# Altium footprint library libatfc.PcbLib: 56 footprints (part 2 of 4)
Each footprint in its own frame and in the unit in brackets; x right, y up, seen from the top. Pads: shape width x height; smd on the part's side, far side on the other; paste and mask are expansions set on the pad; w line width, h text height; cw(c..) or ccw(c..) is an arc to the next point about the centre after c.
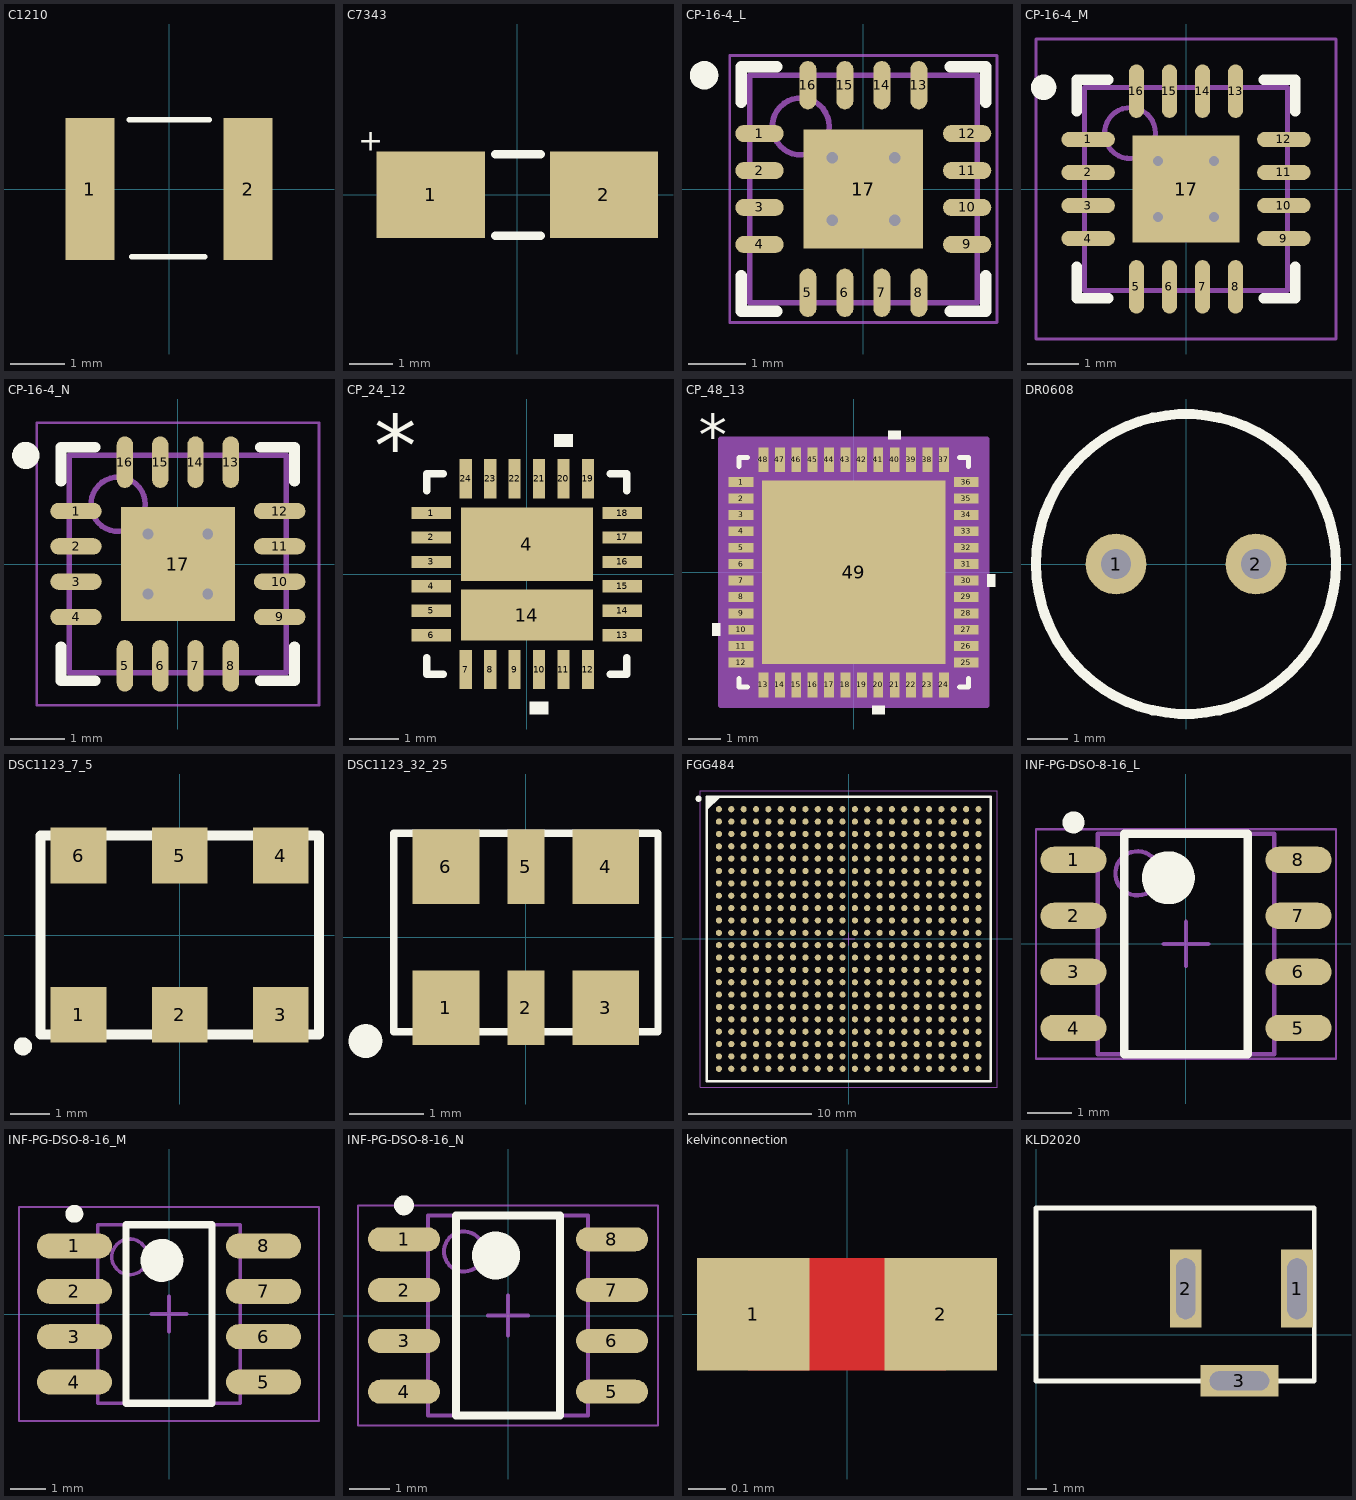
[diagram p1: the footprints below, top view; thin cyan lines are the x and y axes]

## C1210 [mm]
pads (2):
  rect 0.9x2.6 smd: 1(-1.45,0) 2(1.45,0)
Top Overlay:
  lines w0.1: -0.728,1.27 0.737,1.27 ; -0.687,-1.245 0.66,-1.245
3D body: height 0.55, standoff 0, extent -1.524,-1.143 -1.016,1.143
3D body: height 0.55, standoff 0, extent -1.016,-1.143 1.016,1.143
3D body: height 0.55, standoff 0, extent 1.016,-1.143 1.524,1.143

## C7343 [mm]
pads (2):
  rect 2.5x2 smd: 1(-2,0) 2(2,0)
Top Overlay:
  lines w0.2: -0.508,-0.94 0.533,-0.94 ; -0.508,0.94 0.533,0.94
  text "+" at -3.683,1.016 h0.51

## CP-16-4_L [mm] "QFN, 16-Leads, Body 4x4mm, Pitch 0.65mm, Thermal Pad 2.1x2.1mm, IPC High Density"
height 1
pads (17):
  oval 0.85x0.3 smd: 1(-1.825,0.975) 2(-1.825,0.325) 3(-1.825,-0.325) 4(-1.825,-0.975) 9(1.825,-0.975) 10(1.825,-0.325) 11(1.825,0.325) 12(1.825,0.975)
  oval 0.3x0.85 smd: 5(-0.975,-1.825) 6(-0.325,-1.825) 7(0.325,-1.825) 8(0.975,-1.825) 13(0.975,1.825) 14(0.325,1.825) 15(-0.325,1.825) 16(-0.975,1.825)
  rect 2.1x2.1 smd: 17(0,0)
via 0.55,-0.55 diameter 0.5 hole 0.2
via -0.55,-0.55 diameter 0.5 hole 0.2
via 0.55,0.55 diameter 0.5 hole 0.2
via -0.55,0.55 diameter 0.5 hole 0.2
Top Overlay:
  circle w0.25: c-2.8,2 r0.125
  lines w0.2: -2.15,-1.525 -2.15,-2.15 -1.525,-2.15 ; -2.15,1.525 -2.15,2.15 -1.525,2.15 ; 1.525,-2.15 2.15,-2.15 2.15,-1.525 ; 1.525,2.15 2.15,2.15 2.15,1.525
Mechanical 13:
  circle w0.1: c-1.1,1.1 r0.5
  lines w0.1: -2,-2 2,-2 2,2 -2,2 -2,-2
Mechanical 15:
  lines w0.05: -2.35,-2.35 2.35,-2.35 2.35,2.35 -2.35,2.35 -2.35,-2.35
  lines w0.1: -0.5,0 0.5,0 ; 0,-0.5 0,0.5
3D body: height 1, standoff 0, extent -2,-2 2,2

## CP-16-4_M [mm] "QFN, 16-Leads, Body 4x4mm, Pitch 0.65mm, Thermal Pad 2.1x2.1mm, IPC Low Density"
height 1
pads (17):
  oval 1.05x0.3 smd: 1(-1.925,0.975) 2(-1.925,0.325) 3(-1.925,-0.325) 4(-1.925,-0.975) 9(1.925,-0.975) 10(1.925,-0.325) 11(1.925,0.325) 12(1.925,0.975)
  oval 0.3x1.05 smd: 5(-0.975,-1.925) 6(-0.325,-1.925) 7(0.325,-1.925) 8(0.975,-1.925) 13(0.975,1.925) 14(0.325,1.925) 15(-0.325,1.925) 16(-0.975,1.925)
  rect 2.1x2.1 smd: 17(0,0)
via 0.55,-0.55 diameter 0.5 hole 0.2
via -0.55,-0.55 diameter 0.5 hole 0.2
via 0.55,0.55 diameter 0.5 hole 0.2
via -0.55,0.55 diameter 0.5 hole 0.2
Top Overlay:
  circle w0.25: c-2.8,2 r0.125
  lines w0.2: -2.15,-1.525 -2.15,-2.15 -1.525,-2.15 ; -2.15,1.525 -2.15,2.15 -1.525,2.15 ; 1.525,-2.15 2.15,-2.15 2.15,-1.525 ; 1.525,2.15 2.15,2.15 2.15,1.525
Mechanical 13:
  circle w0.1: c-1.1,1.1 r0.5
  lines w0.1: -2,-2 2,-2 2,2 -2,2 -2,-2
Mechanical 15:
  lines w0.05: -2.95,-2.95 2.95,-2.95 2.95,2.95 -2.95,2.95 -2.95,-2.95
  lines w0.1: -0.5,0 0.5,0 ; 0,-0.5 0,0.5
3D body: height 1, standoff 0, extent -2,-2 2,2

## CP-16-4_N [mm] "QFN, 16-Leads, Body 4x4mm, Pitch 0.65mm, Thermal Pad 2.1x2.1mm, IPC Medium Density"
height 1
pads (17):
  oval 0.95x0.3 smd: 1(-1.875,0.975) 2(-1.875,0.325) 3(-1.875,-0.325) 4(-1.875,-0.975) 9(1.875,-0.975) 10(1.875,-0.325) 11(1.875,0.325) 12(1.875,0.975)
  oval 0.3x0.95 smd: 5(-0.975,-1.875) 6(-0.325,-1.875) 7(0.325,-1.875) 8(0.975,-1.875) 13(0.975,1.875) 14(0.325,1.875) 15(-0.325,1.875) 16(-0.975,1.875)
  rect 2.1x2.1 smd: 17(0,0)
via -0.55,0.55 diameter 0.5 hole 0.2
via 0.55,0.55 diameter 0.5 hole 0.2
via -0.55,-0.55 diameter 0.5 hole 0.2
via 0.55,-0.55 diameter 0.5 hole 0.2
Top Overlay:
  circle w0.25: c-2.8,2 r0.125
  lines w0.2: -2.15,-1.525 -2.15,-2.15 -1.525,-2.15 ; -2.15,1.525 -2.15,2.15 -1.525,2.15 ; 1.525,-2.15 2.15,-2.15 2.15,-1.525 ; 1.525,2.15 2.15,2.15 2.15,1.525
Mechanical 13:
  circle w0.1: c-1.1,1.1 r0.5
  lines w0.1: -2,-2 -2,2 2,2 2,-2 -2,-2
Mechanical 15:
  lines w0.05: -2.6,-2.6 -2.6,2.6 2.6,2.6 2.6,-2.6 -2.6,-2.6
  lines w0.1: -0.5,0 0.5,0 ; 0,-0.5 0,0.5
3D body: height 1, standoff 0, extent -2,-2 2,2

## CP_24_12 [mm]
pads (26):
  rect 0.805x0.25 smd: 1(-1.952,1.25) 2(-1.952,0.75) 3(-1.952,0.25) 4(-1.952,-0.25) 5(-1.952,-0.75) 6(-1.952,-1.25) 13(1.952,-1.25) 14(1.952,-0.75) 15(1.952,-0.25) 16(1.952,0.25) 17(1.952,0.75) 18(1.952,1.25)
  rect 2.7x1.5 smd: 4(0,0.61)
  rect 0.25x0.805 smd: 7(-1.25,-1.952) 8(-0.75,-1.952) 9(-0.25,-1.952) 10(0.25,-1.952) 11(0.75,-1.952) 12(1.25,-1.952) 19(1.25,1.952) 20(0.75,1.952) 21(0.25,1.952) 22(-0.25,1.952) 23(-0.75,1.952) 24(-1.25,1.952)
  rect 2.7x1.05 smd: 14(0,-0.838)
Top Overlay:
  region: 0.941,2.609 0.56,2.609 0.56,2.863 0.941,2.863
  region: 0.44,-2.609 0.059,-2.609 0.059,-2.863 0.44,-2.863
  lines w0.152: -2.05,-1.708 -2.05,-2.05 -1.708,-2.05 ; -2.05,1.708 -2.05,2.05 -1.708,2.05 ; 1.708,-2.05 2.05,-2.05 2.05,-1.708 ; 1.708,2.05 2.05,2.05 2.05,1.708
  text "*" at -3.124,2.007 h1.27
Mechanical 13:
  text "*" at -3.124,2.007 h1.27
3D body: height 0.25, standoff 0, extent -2.032,-2.032 2.032,2.032

## CP_48_13 [mm]
pads (49):
  rect 0.755x0.3 smd: 1(-3.433,2.75) 2(-3.433,2.25) 3(-3.433,1.75) 4(-3.433,1.25) 5(-3.433,0.75) 6(-3.433,0.25) 7(-3.433,-0.25) 8(-3.433,-0.75) 9(-3.433,-1.25) 10(-3.433,-1.75) 11(-3.433,-2.25) 12(-3.433,-2.75) 25(3.433,-2.75) 26(3.433,-2.25) 27(3.433,-1.75) 28(3.433,-1.25) 29(3.433,-0.75) 30(3.433,-0.25) 31(3.433,0.25) 32(3.433,0.75) 33(3.433,1.25) 34(3.433,1.75) 35(3.433,2.25) 36(3.433,2.75)
  rect 0.3x0.755 smd: 13(-2.75,-3.433) 14(-2.25,-3.433) 15(-1.75,-3.433) 16(-1.25,-3.433) 17(-0.75,-3.433) 18(-0.25,-3.433) 19(0.25,-3.433) 20(0.75,-3.433) 21(1.25,-3.433) 22(1.75,-3.433) 23(2.25,-3.433) 24(2.75,-3.433) 37(2.75,3.433) 38(2.25,3.433) 39(1.75,3.433) 40(1.25,3.433) 41(0.75,3.433) 42(0.25,3.433) 43(-0.25,3.433) 44(-0.75,3.433) 45(-1.25,3.433) 46(-1.75,3.433) 47(-2.25,3.433) 48(-2.75,3.433)
  rect 5.6x5.6 smd mask-2.781: 49(0,0)
Top Overlay:
  region: 1.441,4.064 1.06,4.064 1.06,4.318 1.441,4.318
  region: 4.064,-0.059 4.318,-0.059 4.318,-0.44 4.064,-0.44
  region: 0.941,-4.064 0.56,-4.064 0.56,-4.318 0.941,-4.318
  region: -4.064,-1.559 -4.318,-1.559 -4.318,-1.94 -4.064,-1.94
  lines w0.152: -3.5,-3.233 -3.5,-3.5 -3.233,-3.5 ; -3.5,3.233 -3.5,3.5 -3.233,3.5 ; 3.233,-3.5 3.5,-3.5 3.5,-3.233 ; 3.233,3.5 3.5,3.5 3.5,3.233
  text "*" at -4.724,3.556 h1.27
Mechanical 13:
  text "*" at -4.724,3.556 h1.27
Mechanical 15:
  region: 4.064,-4.064 -4.064,-4.064 -4.064,4.064 4.064,4.064
  lines w0.152: -4.064,-4.064 4.064,-4.064 4.064,4.064 -4.064,4.064 -4.064,-4.064
3D body: height 0.25, standoff 0, extent 0,0 0.254,0.254
3D body: height 0.76, standoff 0, extent -3.429,-3.429 3.404,3.404

## DR0608 [mil]
pads (2):
  round 60 hole 30: 1(-68.9,0) 2(68.9,0)
Top Overlay:
  circle w10: c0,0 r147.64
3D body "Coilcraft-DR0608.step": height 381.89, standoff -188.98, extent -148.63,-145.63 146.64,149.64

## DSC1123_7_5 [mm]
height 0.85
pads (6):
  rect 1.4x1.4 smd: 1(-2.54,-2) 2(0,-2) 3(2.54,-2) 4(2.54,2) 5(0,2) 6(-2.54,2)
Top Overlay:
  circle w0.254: c-3.937,-2.794 r0.1
  lines w0.254: -3.5,-2.5 3.5,-2.5 3.5,2.5 -3.5,2.5 -3.5,-2.5
3D body: height 0.85, standoff 0, extent -3.429,-2.413 3.429,2.413

## DSC1123_32_25 [mm]
pads (6):
  rect 0.9x1 smd: 1(-1.075,-0.95) 3(1.075,-0.95) 4(1.075,0.95) 6(-1.075,0.95)
  rect 0.5x1 smd: 2(0,-0.95) 5(0,0.95)
Top Overlay:
  circle w0.254: c-2.159,-1.397 r0.1
  lines w0.1: -1.778,-1.27 1.778,-1.27 1.778,1.397 -1.778,1.397 -1.778,-1.27
3D body: height 0.85, standoff 0, extent -1.778,-1.27 1.778,1.397

## FGG484 [mm] "BGA, 484-Balls, Body 23x23mm, Pitch 1mm"
height 2.6
pads (484):
  round 0.5 smd: A1(-10.5,10.5) A2(-9.5,10.5) A3(-8.5,10.5) A4(-7.5,10.5) A5(-6.5,10.5) A6(-5.5,10.5) A7(-4.5,10.5) A8(-3.5,10.5) A9(-2.5,10.5) A10(-1.5,10.5) A11(-0.5,10.5) A12(0.5,10.5) A13(1.5,10.5) A14(2.5,10.5) A15(3.5,10.5) A16(4.5,10.5) A17(5.5,10.5) A18(6.5,10.5) A19(7.5,10.5) A20(8.5,10.5) A21(9.5,10.5) A22(10.5,10.5) AA1(-10.5,-9.5) AA2(-9.5,-9.5) AA3(-8.5,-9.5) AA4(-7.5,-9.5) AA5(-6.5,-9.5) AA6(-5.5,-9.5) AA7(-4.5,-9.5) AA8(-3.5,-9.5) AA9(-2.5,-9.5) AA10(-1.5,-9.5) AA11(-0.5,-9.5) AA12(0.5,-9.5) AA13(1.5,-9.5) AA14(2.5,-9.5) AA15(3.5,-9.5) AA16(4.5,-9.5) AA17(5.5,-9.5) AA18(6.5,-9.5) AA19(7.5,-9.5) AA20(8.5,-9.5) AA21(9.5,-9.5) AA22(10.5,-9.5) AB1(-10.5,-10.5) AB2(-9.5,-10.5) AB3(-8.5,-10.5) AB4(-7.5,-10.5) AB5(-6.5,-10.5) AB6(-5.5,-10.5) AB7(-4.5,-10.5) AB8(-3.5,-10.5) AB9(-2.5,-10.5) AB10(-1.5,-10.5) AB11(-0.5,-10.5) AB12(0.5,-10.5) AB13(1.5,-10.5) AB14(2.5,-10.5) AB15(3.5,-10.5) AB16(4.5,-10.5) AB17(5.5,-10.5) AB18(6.5,-10.5) AB19(7.5,-10.5) AB20(8.5,-10.5) AB21(9.5,-10.5) AB22(10.5,-10.5) B1(-10.5,9.5) B2(-9.5,9.5) B3(-8.5,9.5) B4(-7.5,9.5) B5(-6.5,9.5) B6(-5.5,9.5) B7(-4.5,9.5) B8(-3.5,9.5) B9(-2.5,9.5) B10(-1.5,9.5) B11(-0.5,9.5) B12(0.5,9.5) B13(1.5,9.5) B14(2.5,9.5) B15(3.5,9.5) B16(4.5,9.5) B17(5.5,9.5) B18(6.5,9.5) B19(7.5,9.5) B20(8.5,9.5) B21(9.5,9.5) B22(10.5,9.5) C1(-10.5,8.5) C2(-9.5,8.5) C3(-8.5,8.5) C4(-7.5,8.5) C5(-6.5,8.5) C6(-5.5,8.5) C7(-4.5,8.5) C8(-3.5,8.5) C9(-2.5,8.5) C10(-1.5,8.5) C11(-0.5,8.5) C12(0.5,8.5) C13(1.5,8.5) C14(2.5,8.5) C15(3.5,8.5) C16(4.5,8.5) C17(5.5,8.5) C18(6.5,8.5) C19(7.5,8.5) C20(8.5,8.5) C21(9.5,8.5) C22(10.5,8.5) D1(-10.5,7.5) D2(-9.5,7.5) D3(-8.5,7.5) D4(-7.5,7.5) D5(-6.5,7.5) D6(-5.5,7.5) D7(-4.5,7.5) D8(-3.5,7.5) D9(-2.5,7.5) D10(-1.5,7.5) D11(-0.5,7.5) D12(0.5,7.5) D13(1.5,7.5) D14(2.5,7.5) D15(3.5,7.5) D16(4.5,7.5) D17(5.5,7.5) D18(6.5,7.5) D19(7.5,7.5) D20(8.5,7.5) D21(9.5,7.5) D22(10.5,7.5) E1(-10.5,6.5) E2(-9.5,6.5) E3(-8.5,6.5) E4(-7.5,6.5) E5(-6.5,6.5) E6(-5.5,6.5) E7(-4.5,6.5) E8(-3.5,6.5) E9(-2.5,6.5) E10(-1.5,6.5) E11(-0.5,6.5) E12(0.5,6.5) E13(1.5,6.5) E14(2.5,6.5) E15(3.5,6.5) E16(4.5,6.5) E17(5.5,6.5) E18(6.5,6.5) E19(7.5,6.5) E20(8.5,6.5) E21(9.5,6.5) E22(10.5,6.5) F1(-10.5,5.5) F2(-9.5,5.5) F3(-8.5,5.5) F4(-7.5,5.5) F5(-6.5,5.5) F6(-5.5,5.5) F7(-4.5,5.5) F8(-3.5,5.5) F9(-2.5,5.5) F10(-1.5,5.5) F11(-0.5,5.5) F12(0.5,5.5) F13(1.5,5.5) F14(2.5,5.5) F15(3.5,5.5) F16(4.5,5.5) F17(5.5,5.5) F18(6.5,5.5) F19(7.5,5.5) F20(8.5,5.5) F21(9.5,5.5) F22(10.5,5.5) G1(-10.5,4.5) G2(-9.5,4.5) G3(-8.5,4.5) G4(-7.5,4.5) G5(-6.5,4.5) G6(-5.5,4.5) G7(-4.5,4.5) G8(-3.5,4.5) G9(-2.5,4.5) G10(-1.5,4.5) G11(-0.5,4.5) G12(0.5,4.5) G13(1.5,4.5) G14(2.5,4.5) G15(3.5,4.5) G16(4.5,4.5) G17(5.5,4.5) G18(6.5,4.5) G19(7.5,4.5) G20(8.5,4.5) G21(9.5,4.5) G22(10.5,4.5) H1(-10.5,3.5) H2(-9.5,3.5) H3(-8.5,3.5) H4(-7.5,3.5) H5(-6.5,3.5) H6(-5.5,3.5) H7(-4.5,3.5) H8(-3.5,3.5) H9(-2.5,3.5) H10(-1.5,3.5) H11(-0.5,3.5) H12(0.5,3.5) H13(1.5,3.5) H14(2.5,3.5) H15(3.5,3.5) H16(4.5,3.5) H17(5.5,3.5) H18(6.5,3.5) H19(7.5,3.5) H20(8.5,3.5) H21(9.5,3.5) H22(10.5,3.5) J1(-10.5,2.5) J2(-9.5,2.5) J3(-8.5,2.5) J4(-7.5,2.5) J5(-6.5,2.5) J6(-5.5,2.5) J7(-4.5,2.5) J8(-3.5,2.5) J9(-2.5,2.5) J10(-1.5,2.5) J11(-0.5,2.5) J12(0.5,2.5) J13(1.5,2.5) J14(2.5,2.5) J15(3.5,2.5) J16(4.5,2.5) J17(5.5,2.5) J18(6.5,2.5) J19(7.5,2.5) J20(8.5,2.5) J21(9.5,2.5) J22(10.5,2.5) K1(-10.5,1.5) K2(-9.5,1.5) K3(-8.5,1.5) K4(-7.5,1.5) K5(-6.5,1.5) K6(-5.5,1.5) K7(-4.5,1.5) K8(-3.5,1.5) K9(-2.5,1.5) K10(-1.5,1.5) K11(-0.5,1.5) K12(0.5,1.5) K13(1.5,1.5) K14(2.5,1.5) K15(3.5,1.5) K16(4.5,1.5) K17(5.5,1.5) K18(6.5,1.5) K19(7.5,1.5) K20(8.5,1.5) K21(9.5,1.5) K22(10.5,1.5) L1(-10.5,0.5) L2(-9.5,0.5) L3(-8.5,0.5) L4(-7.5,0.5) L5(-6.5,0.5) L6(-5.5,0.5) L7(-4.5,0.5) L8(-3.5,0.5) L9(-2.5,0.5) L10(-1.5,0.5) L11(-0.5,0.5) L12(0.5,0.5) L13(1.5,0.5) L14(2.5,0.5) L15(3.5,0.5) L16(4.5,0.5) L17(5.5,0.5) L18(6.5,0.5) L19(7.5,0.5) L20(8.5,0.5) L21(9.5,0.5) L22(10.5,0.5) M1(-10.5,-0.5) M2(-9.5,-0.5) M3(-8.5,-0.5) M4(-7.5,-0.5) M5(-6.5,-0.5) M6(-5.5,-0.5) M7(-4.5,-0.5) M8(-3.5,-0.5) M9(-2.5,-0.5) M10(-1.5,-0.5) M11(-0.5,-0.5) M12(0.5,-0.5) M13(1.5,-0.5) M14(2.5,-0.5) M15(3.5,-0.5) M16(4.5,-0.5) M17(5.5,-0.5) M18(6.5,-0.5) M19(7.5,-0.5) M20(8.5,-0.5) M21(9.5,-0.5) M22(10.5,-0.5) N1(-10.5,-1.5) N2(-9.5,-1.5) N3(-8.5,-1.5) N4(-7.5,-1.5) N5(-6.5,-1.5) N6(-5.5,-1.5) N7(-4.5,-1.5) N8(-3.5,-1.5) N9(-2.5,-1.5) N10(-1.5,-1.5) N11(-0.5,-1.5) N12(0.5,-1.5) N13(1.5,-1.5) N14(2.5,-1.5) N15(3.5,-1.5) N16(4.5,-1.5) N17(5.5,-1.5) N18(6.5,-1.5) N19(7.5,-1.5) N20(8.5,-1.5) N21(9.5,-1.5) N22(10.5,-1.5) P1(-10.5,-2.5) P2(-9.5,-2.5) P3(-8.5,-2.5) P4(-7.5,-2.5) P5(-6.5,-2.5) P6(-5.5,-2.5) P7(-4.5,-2.5) P8(-3.5,-2.5) P9(-2.5,-2.5) P10(-1.5,-2.5) P11(-0.5,-2.5) P12(0.5,-2.5) P13(1.5,-2.5) P14(2.5,-2.5) P15(3.5,-2.5) P16(4.5,-2.5) P17(5.5,-2.5) P18(6.5,-2.5) P19(7.5,-2.5) P20(8.5,-2.5) P21(9.5,-2.5) P22(10.5,-2.5) R1(-10.5,-3.5) R2(-9.5,-3.5) R3(-8.5,-3.5) R4(-7.5,-3.5) R5(-6.5,-3.5) R6(-5.5,-3.5) R7(-4.5,-3.5) R8(-3.5,-3.5) R9(-2.5,-3.5) R10(-1.5,-3.5) R11(-0.5,-3.5) R12(0.5,-3.5) R13(1.5,-3.5) R14(2.5,-3.5) R15(3.5,-3.5) R16(4.5,-3.5) R17(5.5,-3.5) R18(6.5,-3.5) R19(7.5,-3.5) R20(8.5,-3.5) R21(9.5,-3.5) R22(10.5,-3.5) T1(-10.5,-4.5) T2(-9.5,-4.5) T3(-8.5,-4.5) T4(-7.5,-4.5) T5(-6.5,-4.5) T6(-5.5,-4.5) T7(-4.5,-4.5) T8(-3.5,-4.5) T9(-2.5,-4.5) T10(-1.5,-4.5) T11(-0.5,-4.5) T12(0.5,-4.5) T13(1.5,-4.5) T14(2.5,-4.5) T15(3.5,-4.5) T16(4.5,-4.5) T17(5.5,-4.5) T18(6.5,-4.5) T19(7.5,-4.5) T20(8.5,-4.5) T21(9.5,-4.5) T22(10.5,-4.5) U1(-10.5,-5.5) U2(-9.5,-5.5) U3(-8.5,-5.5) U4(-7.5,-5.5) U5(-6.5,-5.5) U6(-5.5,-5.5) U7(-4.5,-5.5) U8(-3.5,-5.5) U9(-2.5,-5.5) U10(-1.5,-5.5) U11(-0.5,-5.5) U12(0.5,-5.5) U13(1.5,-5.5) U14(2.5,-5.5) U15(3.5,-5.5) U16(4.5,-5.5) U17(5.5,-5.5) U18(6.5,-5.5) U19(7.5,-5.5) U20(8.5,-5.5) U21(9.5,-5.5) U22(10.5,-5.5) V1(-10.5,-6.5) V2(-9.5,-6.5) V3(-8.5,-6.5) V4(-7.5,-6.5) V5(-6.5,-6.5) V6(-5.5,-6.5) V7(-4.5,-6.5) V8(-3.5,-6.5) V9(-2.5,-6.5) V10(-1.5,-6.5) V11(-0.5,-6.5) V12(0.5,-6.5) V13(1.5,-6.5) V14(2.5,-6.5) V15(3.5,-6.5) V16(4.5,-6.5) V17(5.5,-6.5) V18(6.5,-6.5) V19(7.5,-6.5) V20(8.5,-6.5) V21(9.5,-6.5) V22(10.5,-6.5) W1(-10.5,-7.5) W2(-9.5,-7.5) W3(-8.5,-7.5) W4(-7.5,-7.5) W5(-6.5,-7.5) W6(-5.5,-7.5) W7(-4.5,-7.5) W8(-3.5,-7.5) W9(-2.5,-7.5) W10(-1.5,-7.5) W11(-0.5,-7.5) W12(0.5,-7.5) W13(1.5,-7.5) W14(2.5,-7.5) W15(3.5,-7.5) W16(4.5,-7.5) W17(5.5,-7.5) W18(6.5,-7.5) W19(7.5,-7.5) W20(8.5,-7.5) W21(9.5,-7.5) W22(10.5,-7.5) Y1(-10.5,-8.5) Y2(-9.5,-8.5) Y3(-8.5,-8.5) Y4(-7.5,-8.5) Y5(-6.5,-8.5) Y6(-5.5,-8.5) Y7(-4.5,-8.5) Y8(-3.5,-8.5) Y9(-2.5,-8.5) Y10(-1.5,-8.5) Y11(-0.5,-8.5) Y12(0.5,-8.5) Y13(1.5,-8.5) Y14(2.5,-8.5) Y15(3.5,-8.5) Y16(4.5,-8.5) Y17(5.5,-8.5) Y18(6.5,-8.5) Y19(7.5,-8.5) Y20(8.5,-8.5) Y21(9.5,-8.5) Y22(10.5,-8.5)
Top Overlay:
  circle w0.25: c-12.15,11.35 r0.125
  region: -10.5,11.5 -11.5,10.5 -11.5,11.5
  lines w0.2: -11.5,10.5 -10.5,11.5 ; -11.5,-11.5 -11.5,11.5 11.5,11.5 11.5,-11.5 -11.5,-11.5
Mechanical 13:
  lines w0.1: -11.5,-11.5 -11.5,11.5 11.5,11.5 11.5,-11.5 -11.5,-11.5
Mechanical 15:
  lines w0.05: -12,-12 -12,12 12,12 12,-12 -12,-12
  lines w0.1: -0.5,0 0.5,0 ; 0,-0.5 0,0.5
3D body: height 2.6, standoff 0.35, extent -11.5,-11.5 11.5,11.5

## INF-PG-DSO-8-16_L [mm] "SOP, 8-Leads, Body 4.9x3.9mm, Pitch 1.27mm, IPC High Density"
height 1.75
pads (8):
  oval 1.5x0.6 smd: 1(-2.55,1.905) 2(-2.55,0.635) 3(-2.55,-0.635) 4(-2.55,-1.905) 5(2.55,-1.905) 6(2.55,-0.635) 7(2.55,0.635) 8(2.55,1.905)
Top Overlay:
  circle w0.6: c-0.4,1.5 r0.3
  circle w0.25: c-2.55,2.755 r0.125
  lines w0.2: -1.4,-2.5 1.4,-2.5 1.4,2.5 -1.4,2.5 -1.4,-2.5
Mechanical 13:
  circle w0.1: c-1.1,1.6 r0.5
  lines w0.1: -2,-2.5 2,-2.5 2,2.5 -2,2.5 -2,-2.5
Mechanical 15:
  lines w0.05: -3.4,-2.6 3.4,-2.6 3.4,2.6 -3.4,2.6 -3.4,-2.6
  lines w0.1: -0.5,0 0.5,0 ; 0,-0.5 0,0.5
3D body: height 1.75, standoff 0.11, extent -2,-2.5 2,2.5

## INF-PG-DSO-8-16_M [mm] "SOP, 8-Leads, Body 4.9x3.9mm, Pitch 1.27mm, IPC Low Density"
height 1.75
pads (8):
  oval 2.1x0.7 smd: 1(-2.65,1.905) 2(-2.65,0.635) 3(-2.65,-0.635) 4(-2.65,-1.905) 5(2.65,-1.905) 6(2.65,-0.635) 7(2.65,0.635) 8(2.65,1.905)
Top Overlay:
  circle w0.25: c-2.65,2.805 r0.125
  circle w0.6: c-0.2,1.5 r0.3
  lines w0.2: -1.2,-2.5 -1.2,2.5 1.2,2.5 1.2,-2.5 -1.2,-2.5
Mechanical 13:
  circle w0.1: c-1.1,1.6 r0.5
  lines w0.1: -2,-2.5 -2,2.5 2,2.5 2,-2.5 -2,-2.5
Mechanical 15:
  lines w0.05: -4.2,-3 -4.2,3 4.2,3 4.2,-3 -4.2,-3
  lines w0.1: -0.5,0 0.5,0 ; 0,-0.5 0,0.5
3D body: height 1.75, standoff 0.11, extent -2,-2.5 2,2.5

## INF-PG-DSO-8-16_N [mm] "SOP, 8-Leads, Body 4.9x3.9mm, Pitch 1.27mm, IPC Medium Density"
height 1.75
pads (8):
  oval 1.8x0.6 smd: 1(-2.6,1.905) 2(-2.6,0.635) 3(-2.6,-0.635) 4(-2.6,-1.905) 5(2.6,-1.905) 6(2.6,-0.635) 7(2.6,0.635) 8(2.6,1.905)
Top Overlay:
  circle w0.25: c-2.6,2.755 r0.125
  circle w0.6: c-0.3,1.5 r0.3
  lines w0.2: -1.3,-2.5 -1.3,2.5 1.3,2.5 1.3,-2.5 -1.3,-2.5
Mechanical 13:
  circle w0.1: c-1.1,1.6 r0.5
  lines w0.1: -2,-2.5 -2,2.5 2,2.5 2,-2.5 -2,-2.5
Mechanical 15:
  lines w0.05: -3.75,-2.75 -3.75,2.75 3.75,2.75 3.75,-2.75 -3.75,-2.75
  lines w0.1: -0.5,0 0.5,0 ; 0,-0.5 0,0.5
3D body: height 1.75, standoff 0.11, extent -2,-2.5 2,2.5

## kelvinconnection [mil]
pads (2):
  rect 12x12 smd: 1(-10,0) 2(10,0)
Top Layer:
  lines w12: -10,0 10,0

## KLD2020 [mm]
pads (3):
  rect 1.651x4.064 hole 1 slot 3.175 at 90 deg: 1(13.6,2.4) 2(7.8,2.4)
  rect 4.064x1.651 hole 1 slot 3.1 at 0 deg: 3(10.6,-2.4)
Top Overlay:
  lines w0.254: 0,-2.4 14.5,-2.4 14.5,6.6 0,6.6 0,-2.4
3D body "STEP-694108301002-rev1.stp": height 10.94, standoff -3.56, extent 0.082,-2.485 14.582,7.015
